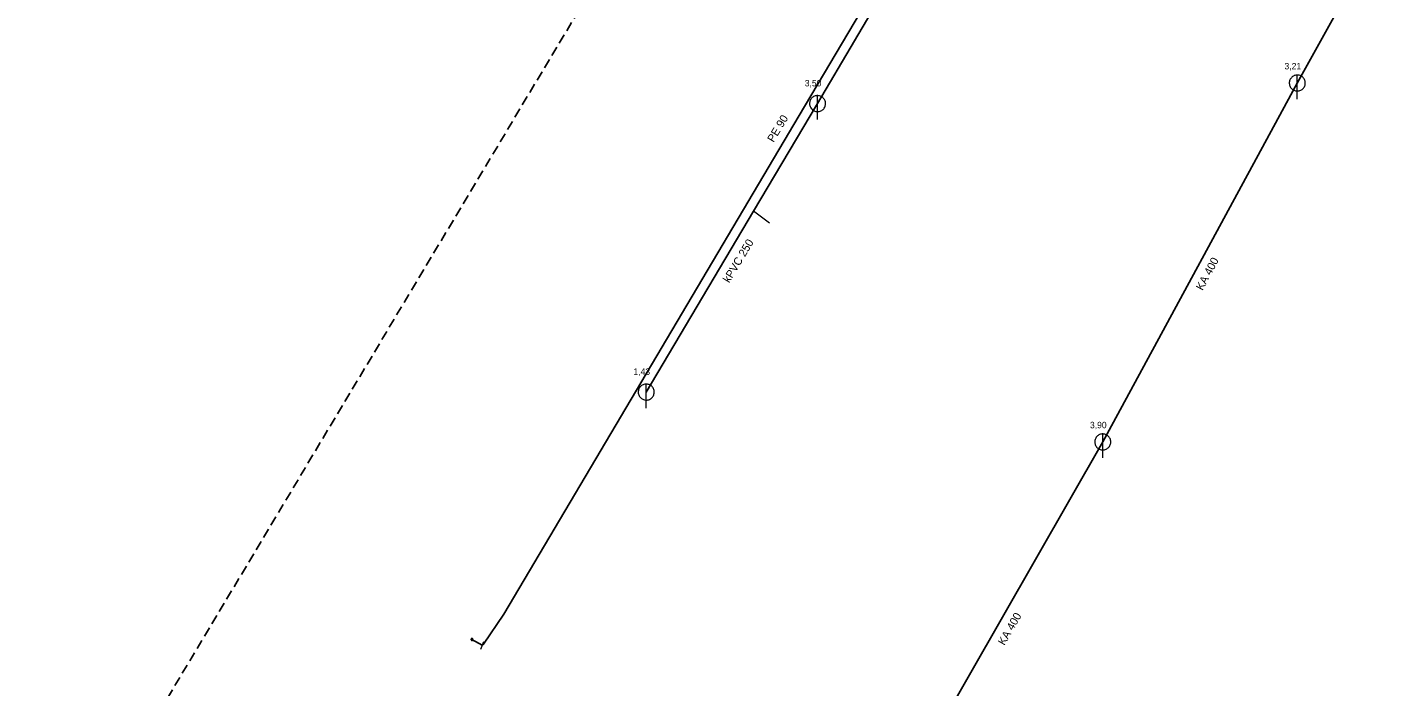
# Model space of a CAD drawing. Extents: x -724358 to -723714, y -973310 to -972026.
# Drawn here: x -724358.4 to -724189.5, y -973117.7 to -973035.2 of the extents above; entities that cross this region are included whole.
import ezdxf

# ---------------------------------------------------------------- set-up
doc = ezdxf.new("R2010")
doc.units = 0
doc.header["$LTSCALE"] = 0.4
doc.linetypes.add('MEDIUM_DASHED', pattern=[4.5, 3, -1.5])
for name, color, linetype, lineweight in [('1', 7, 'Continuous', 13), ('11', 7, 'Continuous', 13), ('14', 7, 'Continuous', 13), ('17', 7, 'Continuous', 25), ('22', 7, 'Continuous', 13), ('34', 7, 'Continuous', 13), ('9', 7, 'Continuous', 13)]:
    doc.layers.add(name, color=color, linetype=linetype, lineweight=lineweight)

msp = doc.modelspace()

# ---------------------------------------------------------------- linework, layer by layer
at = {"layer": '1', "linetype": 'MEDIUM_DASHED', "lineweight": 25}
msp.add_lwpolyline([(-723809.944, -972026.35), (-723713.647, -972034.723), (-723734.581, -972361.295), (-724123.956, -973039.561), (-724241.187, -973309.611), (-724358.418, -973148.418), (-723860.186, -972315.24)], close=True, dxfattribs=at)
at = {"layer": '11'}
msp.add_line((-724265.649, -973059.68), (-724267.625, -973058.219), dxfattribs=at)
at = {"layer": '14', "lineweight": 25}
msp.add_line((-724223.989, -973087.05), (-724199.68, -973042.18), dxfattribs=at)
for points in [[(-724199.68, -973042.18), (-724175.35, -972998.37), (-724168.649, -972968.05), (-724140.149, -972952.289), (-724129.112, -972956.537), (-724090.03, -972946.64), (-724084.339, -972950.81)], [(-724259.629, -973044.75), (-724241.14, -973013.379), (-724225.039, -972985.84)], [(-724281.039, -973080.82), (-724267.625, -973058.219), (-724259.629, -973044.75)], [(-724303.17, -973133.059), (-724249.059, -973130.899), (-724223.989, -973087.05)]]:
    msp.add_lwpolyline(points, dxfattribs=at)
at = {"layer": '17'}
msp.add_line((-724301.535, -973112.48), (-724302.815, -973111.739), dxfattribs=at)
msp.add_lwpolyline([(-724227.079, -972987.531), (-724247.38, -973021.691), (-724261.945, -973046.239), (-724298.824, -973108.59), (-724301.364, -973112.34), (-724301.535, -973112.48)], dxfattribs=at)
at = {"layer": '22'}
for p, q in [((-724199.68, -973044.18), (-724199.679, -973041.18)), ((-724259.629, -973046.75), (-724259.628, -973043.75)), ((-724281.039, -973082.82), (-724281.038, -973079.82)), ((-724223.989, -973089.05), (-724223.988, -973086.05))]:
    msp.add_line(p, q, dxfattribs=at)
for points in [[(-724198.68, -973042.18), (-724198.685, -973042.071), (-724198.703, -973041.963), (-724198.733, -973041.857), (-724198.773, -973041.756), (-724198.825, -973041.659), (-724198.887, -973041.569), (-724198.959, -973041.486), (-724199.039, -973041.412), (-724199.127, -973041.346), (-724199.221, -973041.291), (-724199.321, -973041.246), (-724199.426, -973041.213), (-724199.533, -973041.191), (-724199.642, -973041.181), (-724199.752, -973041.183), (-724199.86, -973041.197), (-724199.967, -973041.222), (-724200.07, -973041.259), (-724200.168, -973041.308), (-724200.26, -973041.366), (-724200.346, -973041.435), (-724200.423, -973041.512), (-724200.492, -973041.598), (-724200.551, -973041.69), (-724200.599, -973041.788), (-724200.636, -973041.891), (-724200.662, -973041.998), (-724200.676, -973042.106), (-724200.679, -973042.216), (-724200.669, -973042.325), (-724200.648, -973042.432), (-724200.614, -973042.536), (-724200.57, -973042.636), (-724200.515, -973042.731), (-724200.449, -973042.819), (-724200.375, -973042.899), (-724200.292, -973042.971), (-724200.202, -973043.033), (-724200.106, -973043.085), (-724200.004, -973043.126), (-724199.899, -973043.156), (-724199.791, -973043.174), (-724199.681, -973043.18), (-724199.572, -973043.174), (-724199.464, -973043.156), (-724199.359, -973043.127), (-724199.257, -973043.086), (-724199.16, -973043.034), (-724199.07, -973042.972), (-724198.987, -973042.901), (-724198.912, -973042.821), (-724198.847, -973042.733), (-724198.791, -973042.639), (-724198.747, -973042.539), (-724198.713, -973042.435), (-724198.691, -973042.327), (-724198.681, -973042.218)], [(-724258.629, -973044.75), (-724258.634, -973044.641), (-724258.652, -973044.533), (-724258.682, -973044.427), (-724258.722, -973044.326), (-724258.774, -973044.229), (-724258.836, -973044.139), (-724258.908, -973044.056), (-724258.988, -973043.982), (-724259.076, -973043.916), (-724259.17, -973043.861), (-724259.27, -973043.816), (-724259.375, -973043.783), (-724259.482, -973043.761), (-724259.591, -973043.751), (-724259.701, -973043.753), (-724259.809, -973043.767), (-724259.916, -973043.792), (-724260.019, -973043.829), (-724260.117, -973043.878), (-724260.209, -973043.936), (-724260.295, -973044.005), (-724260.372, -973044.082), (-724260.441, -973044.168), (-724260.5, -973044.26), (-724260.548, -973044.358), (-724260.585, -973044.461), (-724260.611, -973044.568), (-724260.625, -973044.676), (-724260.628, -973044.786), (-724260.618, -973044.895), (-724260.597, -973045.002), (-724260.563, -973045.106), (-724260.519, -973045.206), (-724260.464, -973045.301), (-724260.398, -973045.389), (-724260.324, -973045.469), (-724260.241, -973045.541), (-724260.151, -973045.603), (-724260.055, -973045.655), (-724259.953, -973045.696), (-724259.848, -973045.726), (-724259.74, -973045.744), (-724259.63, -973045.75), (-724259.521, -973045.744), (-724259.413, -973045.726), (-724259.308, -973045.697), (-724259.206, -973045.656), (-724259.109, -973045.604), (-724259.019, -973045.542), (-724258.936, -973045.471), (-724258.861, -973045.391), (-724258.796, -973045.303), (-724258.74, -973045.209), (-724258.696, -973045.109), (-724258.662, -973045.005), (-724258.64, -973044.897), (-724258.63, -973044.788)], [(-724280.039, -973080.82), (-724280.044, -973080.711), (-724280.062, -973080.603), (-724280.092, -973080.497), (-724280.132, -973080.396), (-724280.184, -973080.299), (-724280.246, -973080.209), (-724280.318, -973080.126), (-724280.398, -973080.052), (-724280.486, -973079.986), (-724280.58, -973079.931), (-724280.68, -973079.886), (-724280.785, -973079.853), (-724280.892, -973079.831), (-724281.001, -973079.821), (-724281.111, -973079.823), (-724281.219, -973079.837), (-724281.326, -973079.862), (-724281.429, -973079.899), (-724281.527, -973079.948), (-724281.619, -973080.006), (-724281.705, -973080.075), (-724281.782, -973080.152), (-724281.851, -973080.238), (-724281.91, -973080.33), (-724281.958, -973080.428), (-724281.995, -973080.531), (-724282.021, -973080.638), (-724282.035, -973080.746), (-724282.038, -973080.856), (-724282.028, -973080.965), (-724282.007, -973081.072), (-724281.973, -973081.176), (-724281.929, -973081.276), (-724281.874, -973081.371), (-724281.808, -973081.459), (-724281.734, -973081.539), (-724281.651, -973081.611), (-724281.561, -973081.673), (-724281.465, -973081.725), (-724281.363, -973081.766), (-724281.258, -973081.796), (-724281.15, -973081.814), (-724281.04, -973081.82), (-724280.931, -973081.814), (-724280.823, -973081.796), (-724280.718, -973081.767), (-724280.616, -973081.726), (-724280.519, -973081.674), (-724280.429, -973081.612), (-724280.346, -973081.541), (-724280.271, -973081.461), (-724280.206, -973081.373), (-724280.15, -973081.279), (-724280.106, -973081.179), (-724280.072, -973081.075), (-724280.05, -973080.967), (-724280.04, -973080.858)], [(-724222.989, -973087.05), (-724222.994, -973086.941), (-724223.012, -973086.833), (-724223.042, -973086.727), (-724223.082, -973086.626), (-724223.134, -973086.529), (-724223.196, -973086.439), (-724223.268, -973086.356), (-724223.348, -973086.282), (-724223.436, -973086.216), (-724223.53, -973086.161), (-724223.63, -973086.116), (-724223.735, -973086.083), (-724223.842, -973086.061), (-724223.951, -973086.051), (-724224.061, -973086.053), (-724224.169, -973086.067), (-724224.276, -973086.092), (-724224.379, -973086.129), (-724224.477, -973086.178), (-724224.569, -973086.236), (-724224.655, -973086.305), (-724224.732, -973086.382), (-724224.801, -973086.468), (-724224.86, -973086.56), (-724224.908, -973086.658), (-724224.945, -973086.761), (-724224.971, -973086.868), (-724224.985, -973086.976), (-724224.988, -973087.086), (-724224.978, -973087.195), (-724224.957, -973087.302), (-724224.923, -973087.406), (-724224.879, -973087.506), (-724224.824, -973087.601), (-724224.758, -973087.689), (-724224.684, -973087.769), (-724224.601, -973087.841), (-724224.511, -973087.903), (-724224.415, -973087.955), (-724224.313, -973087.996), (-724224.208, -973088.026), (-724224.1, -973088.044), (-724223.99, -973088.05), (-724223.881, -973088.044), (-724223.773, -973088.026), (-724223.668, -973087.997), (-724223.566, -973087.956), (-724223.469, -973087.904), (-724223.379, -973087.842), (-724223.296, -973087.771), (-724223.221, -973087.691), (-724223.156, -973087.603), (-724223.1, -973087.509), (-724223.056, -973087.409), (-724223.022, -973087.305), (-724223, -973087.197), (-724222.99, -973087.088)]]:
    msp.add_lwpolyline(points, close=True, dxfattribs=at)
at = {"layer": '34'}
msp.add_line((-724301.72, -973112.944), (-724301.348, -973112.016), dxfattribs=at)
at = {"layer": '9'}
for points in [[(-724302.941, -973111.739), (-724302.941, -973111.752), (-724302.938, -973111.765), (-724302.936, -973111.778), (-724302.931, -973111.79), (-724302.924, -973111.802), (-724302.918, -973111.813), (-724302.909, -973111.823), (-724302.899, -973111.833), (-724302.889, -973111.841), (-724302.879, -973111.848), (-724302.867, -973111.854), (-724302.855, -973111.859), (-724302.842, -973111.862), (-724302.828, -973111.864), (-724302.816, -973111.866), (-724302.803, -973111.865), (-724302.789, -973111.863), (-724302.777, -973111.86), (-724302.764, -973111.855), (-724302.752, -973111.849), (-724302.742, -973111.842), (-724302.732, -973111.834), (-724302.722, -973111.824), (-724302.713, -973111.814), (-724302.706, -973111.803), (-724302.701, -973111.791), (-724302.696, -973111.779), (-724302.693, -973111.766), (-724302.691, -973111.753), (-724302.688, -973111.74), (-724302.69, -973111.727), (-724302.691, -973111.714), (-724302.695, -973111.701), (-724302.7, -973111.689), (-724302.705, -973111.677), (-724302.713, -973111.666), (-724302.72, -973111.656), (-724302.73, -973111.646), (-724302.74, -973111.638), (-724302.752, -973111.631), (-724302.764, -973111.625), (-724302.776, -973111.62), (-724302.789, -973111.617), (-724302.801, -973111.615), (-724302.815, -973111.614), (-724302.828, -973111.614), (-724302.84, -973111.616), (-724302.853, -973111.619), (-724302.865, -973111.624), (-724302.877, -973111.63), (-724302.889, -973111.637), (-724302.899, -973111.645), (-724302.909, -973111.655), (-724302.916, -973111.665), (-724302.924, -973111.676), (-724302.929, -973111.688), (-724302.934, -973111.7), (-724302.938, -973111.713), (-724302.94, -973111.726)], [(-724302.921, -973111.739), (-724302.921, -973111.75), (-724302.919, -973111.761), (-724302.916, -973111.772), (-724302.913, -973111.782), (-724302.907, -973111.792), (-724302.902, -973111.801), (-724302.894, -973111.81), (-724302.887, -973111.818), (-724302.877, -973111.825), (-724302.869, -973111.831), (-724302.858, -973111.836), (-724302.848, -973111.84), (-724302.838, -973111.843), (-724302.826, -973111.846), (-724302.816, -973111.846), (-724302.804, -973111.846), (-724302.794, -973111.844), (-724302.782, -973111.841), (-724302.772, -973111.837), (-724302.762, -973111.832), (-724302.754, -973111.826), (-724302.745, -973111.819), (-724302.737, -973111.811), (-724302.73, -973111.802), (-724302.723, -973111.793), (-724302.718, -973111.783), (-724302.715, -973111.773), (-724302.712, -973111.762), (-724302.71, -973111.751), (-724302.708, -973111.74), (-724302.708, -973111.729), (-724302.71, -973111.718), (-724302.713, -973111.707), (-724302.718, -973111.697), (-724302.723, -973111.687), (-724302.728, -973111.678), (-724302.735, -973111.669), (-724302.744, -973111.661), (-724302.752, -973111.654), (-724302.762, -973111.648), (-724302.772, -973111.643), (-724302.781, -973111.639), (-724302.793, -973111.636), (-724302.803, -973111.634), (-724302.815, -973111.634), (-724302.826, -973111.633), (-724302.837, -973111.635), (-724302.848, -973111.638), (-724302.857, -973111.642), (-724302.867, -973111.647), (-724302.877, -973111.653), (-724302.886, -973111.66), (-724302.894, -973111.668), (-724302.901, -973111.677), (-724302.906, -973111.686), (-724302.911, -973111.696), (-724302.916, -973111.706), (-724302.919, -973111.717), (-724302.921, -973111.728)], [(-724302.902, -973111.739), (-724302.902, -973111.748), (-724302.901, -973111.757), (-724302.897, -973111.766), (-724302.894, -973111.774), (-724302.891, -973111.782), (-724302.886, -973111.79), (-724302.879, -973111.797), (-724302.874, -973111.803), (-724302.867, -973111.809), (-724302.858, -973111.814), (-724302.85, -973111.818), (-724302.843, -973111.821), (-724302.833, -973111.824), (-724302.825, -973111.825), (-724302.816, -973111.827), (-724302.806, -973111.826), (-724302.798, -973111.825), (-724302.789, -973111.822), (-724302.781, -973111.819), (-724302.772, -973111.815), (-724302.764, -973111.81), (-724302.757, -973111.804), (-724302.752, -973111.798), (-724302.745, -973111.791), (-724302.74, -973111.783), (-724302.737, -973111.775), (-724302.733, -973111.767), (-724302.73, -973111.758), (-724302.73, -973111.749), (-724302.727, -973111.74), (-724302.728, -973111.731), (-724302.73, -973111.722), (-724302.732, -973111.713), (-724302.735, -973111.705), (-724302.74, -973111.697), (-724302.745, -973111.689), (-724302.75, -973111.682), (-724302.757, -973111.676), (-724302.764, -973111.67), (-724302.772, -973111.665), (-724302.779, -973111.661), (-724302.788, -973111.658), (-724302.796, -973111.655), (-724302.806, -973111.654), (-724302.815, -973111.653), (-724302.823, -973111.653), (-724302.833, -973111.654), (-724302.842, -973111.657), (-724302.85, -973111.66), (-724302.857, -973111.664), (-724302.865, -973111.669), (-724302.872, -973111.675), (-724302.879, -973111.681), (-724302.884, -973111.688), (-724302.889, -973111.696), (-724302.894, -973111.704), (-724302.897, -973111.712), (-724302.899, -973111.721), (-724302.901, -973111.73)], [(-724302.882, -973111.739), (-724302.882, -973111.746), (-724302.88, -973111.753), (-724302.879, -973111.76), (-724302.877, -973111.766), (-724302.874, -973111.772), (-724302.87, -973111.778), (-724302.865, -973111.784), (-724302.86, -973111.789), (-724302.855, -973111.793), (-724302.848, -973111.797), (-724302.843, -973111.8), (-724302.837, -973111.803), (-724302.83, -973111.804), (-724302.823, -973111.807), (-724302.816, -973111.807), (-724302.808, -973111.807), (-724302.801, -973111.805), (-724302.794, -973111.804), (-724302.789, -973111.801), (-724302.781, -973111.798), (-724302.777, -973111.794), (-724302.771, -973111.79), (-724302.766, -973111.785), (-724302.762, -973111.779), (-724302.757, -973111.773), (-724302.754, -973111.767), (-724302.752, -973111.761), (-724302.75, -973111.754), (-724302.749, -973111.747), (-724302.747, -973111.74), (-724302.747, -973111.733), (-724302.749, -973111.726), (-724302.75, -973111.719), (-724302.754, -973111.713), (-724302.757, -973111.706), (-724302.761, -973111.701), (-724302.764, -973111.695), (-724302.769, -973111.69), (-724302.776, -973111.686), (-724302.781, -973111.682), (-724302.788, -973111.679), (-724302.794, -973111.676), (-724302.801, -973111.674), (-724302.808, -973111.673), (-724302.815, -973111.673), (-724302.821, -973111.673), (-724302.828, -973111.673), (-724302.835, -973111.675), (-724302.842, -973111.678), (-724302.848, -973111.681), (-724302.853, -973111.685), (-724302.86, -973111.689), (-724302.865, -973111.694), (-724302.869, -973111.7), (-724302.872, -973111.705), (-724302.875, -973111.712), (-724302.879, -973111.718), (-724302.879, -973111.725), (-724302.882, -973111.732)], [(-724302.862, -973111.739), (-724302.862, -973111.744), (-724302.862, -973111.749), (-724302.86, -973111.754), (-724302.858, -973111.758), (-724302.857, -973111.763), (-724302.853, -973111.767), (-724302.85, -973111.77), (-724302.847, -973111.774), (-724302.843, -973111.777), (-724302.84, -973111.78), (-724302.835, -973111.782), (-724302.83, -973111.784), (-724302.826, -973111.785), (-724302.821, -973111.787), (-724302.816, -973111.787), (-724302.811, -973111.787), (-724302.806, -973111.786), (-724302.801, -973111.785), (-724302.796, -973111.783), (-724302.791, -973111.781), (-724302.788, -973111.778), (-724302.784, -973111.775), (-724302.781, -973111.771), (-724302.777, -973111.768), (-724302.774, -973111.764), (-724302.772, -973111.759), (-724302.771, -973111.755), (-724302.769, -973111.75), (-724302.769, -973111.745), (-724302.767, -973111.74), (-724302.767, -973111.735), (-724302.769, -973111.73), (-724302.769, -973111.725), (-724302.772, -973111.721), (-724302.774, -973111.716), (-724302.777, -973111.712), (-724302.779, -973111.708), (-724302.782, -973111.705), (-724302.786, -973111.702), (-724302.791, -973111.699), (-724302.796, -973111.697), (-724302.799, -973111.695), (-724302.804, -973111.694), (-724302.809, -973111.693), (-724302.815, -973111.693), (-724302.82, -973111.693), (-724302.825, -973111.694), (-724302.83, -973111.694), (-724302.833, -973111.696), (-724302.838, -973111.698), (-724302.843, -973111.701), (-724302.845, -973111.704), (-724302.85, -973111.707), (-724302.852, -973111.711), (-724302.855, -973111.715), (-724302.857, -973111.72), (-724302.86, -973111.724), (-724302.86, -973111.729), (-724302.862, -973111.734)], [(-724302.842, -973111.739), (-724302.842, -973111.742), (-724302.843, -973111.745), (-724302.842, -973111.747), (-724302.84, -973111.75), (-724302.84, -973111.753), (-724302.838, -973111.755), (-724302.835, -973111.757), (-724302.833, -973111.759), (-724302.831, -973111.761), (-724302.83, -973111.763), (-724302.826, -973111.765), (-724302.823, -973111.766), (-724302.821, -973111.766), (-724302.818, -973111.767), (-724302.816, -973111.767), (-724302.813, -973111.767), (-724302.809, -973111.767), (-724302.806, -973111.766), (-724302.804, -973111.765), (-724302.801, -973111.764), (-724302.799, -973111.762), (-724302.796, -973111.76), (-724302.794, -973111.758), (-724302.794, -973111.756), (-724302.791, -973111.754), (-724302.791, -973111.751), (-724302.789, -973111.748), (-724302.789, -973111.746), (-724302.788, -973111.743), (-724302.786, -973111.74), (-724302.788, -973111.737), (-724302.788, -973111.734), (-724302.789, -973111.731), (-724302.789, -973111.729), (-724302.791, -973111.726), (-724302.793, -973111.724), (-724302.794, -973111.721), (-724302.796, -973111.719), (-724302.799, -973111.718), (-724302.801, -973111.716), (-724302.803, -973111.715), (-724302.806, -973111.714), (-724302.808, -973111.713), (-724302.811, -973111.713), (-724302.815, -973111.712), (-724302.818, -973111.713), (-724302.821, -973111.712), (-724302.823, -973111.714), (-724302.826, -973111.714), (-724302.828, -973111.715), (-724302.83, -973111.717), (-724302.833, -973111.718), (-724302.835, -973111.72), (-724302.837, -973111.723), (-724302.838, -973111.725), (-724302.84, -973111.728), (-724302.84, -973111.73), (-724302.842, -973111.733), (-724302.842, -973111.736)], [(-724302.823, -973111.739), (-724302.823, -973111.741), (-724302.823, -973111.741), (-724302.821, -973111.741), (-724302.821, -973111.743), (-724302.823, -973111.744), (-724302.821, -973111.744), (-724302.821, -973111.744), (-724302.821, -973111.746), (-724302.821, -973111.746), (-724302.82, -973111.747), (-724302.818, -973111.747), (-724302.818, -973111.747), (-724302.818, -973111.748), (-724302.816, -973111.748), (-724302.816, -973111.748), (-724302.815, -973111.748), (-724302.813, -973111.748), (-724302.813, -973111.747), (-724302.813, -973111.747), (-724302.811, -973111.747), (-724302.811, -973111.746), (-724302.811, -973111.746), (-724302.809, -973111.745), (-724302.809, -973111.745), (-724302.808, -973111.744), (-724302.808, -973111.743), (-724302.806, -973111.742), (-724302.806, -973111.742), (-724302.806, -973111.741), (-724302.806, -973111.74), (-724302.806, -973111.739), (-724302.806, -973111.738), (-724302.806, -973111.738), (-724302.808, -973111.737), (-724302.808, -973111.736), (-724302.808, -973111.735), (-724302.808, -973111.735), (-724302.809, -973111.734), (-724302.809, -973111.734), (-724302.811, -973111.733), (-724302.811, -973111.733), (-724302.813, -973111.732), (-724302.813, -973111.732), (-724302.813, -973111.732), (-724302.815, -973111.732), (-724302.816, -973111.732), (-724302.816, -973111.732), (-724302.816, -973111.732), (-724302.818, -973111.733), (-724302.818, -973111.732), (-724302.82, -973111.734), (-724302.82, -973111.734), (-724302.821, -973111.734), (-724302.821, -973111.734), (-724302.821, -973111.736), (-724302.821, -973111.737), (-724302.821, -973111.738), (-724302.823, -973111.738), (-724302.823, -973111.739)]]:
    msp.add_lwpolyline(points, close=True, dxfattribs=at)

# ---------------------------------------------------------------- texts
at = {"layer": '1'}
for s, p in [('3,21', (-724201.279, -973040.468)), ('3,50', (-724261.229, -973042.597)), ('1,43', (-724282.639, -973078.667)), ('3,90', (-724225.589, -973085.338))]:
    msp.add_text(s, height=0.8, dxfattribs=at).set_placement(p)
for s, rotation, p in [('PE 90 ', 59, (-724265.127, -973049.676)), ('kPVC 250', 59, (-724270.668, -973067.237)), ('KA 400', 62, (-724211.518, -973068.197)), ('KA 400', 60, (-724236.289, -973112.564))]:
    msp.add_text(s, height=1, rotation=rotation, dxfattribs=at).set_placement(p)

doc.saveas('drawing.dxf')
